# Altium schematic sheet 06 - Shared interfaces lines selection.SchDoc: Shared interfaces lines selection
size A3; PageSetup: Record=PageOptions¦CenterHorizontal=True¦CenterVertical=True¦PrintScale=0.70¦XCorrection=1.00¦YCorrection=1.00¦PrintKind=0¦BorderSize=5000000¦LeftOffset=0¦BottomOffset=0¦Orientation=2¦PaperLength=4200¦PaperWidth=2970¦Scale=100¦PaperSource=7¦PrintQuality=600¦MediaType=1¦DitherType=10¦PaperKind=A4¦PrintScaleMode=1; Author: Juan Anzola; SheetNumber: 6; SheetTotal: 20
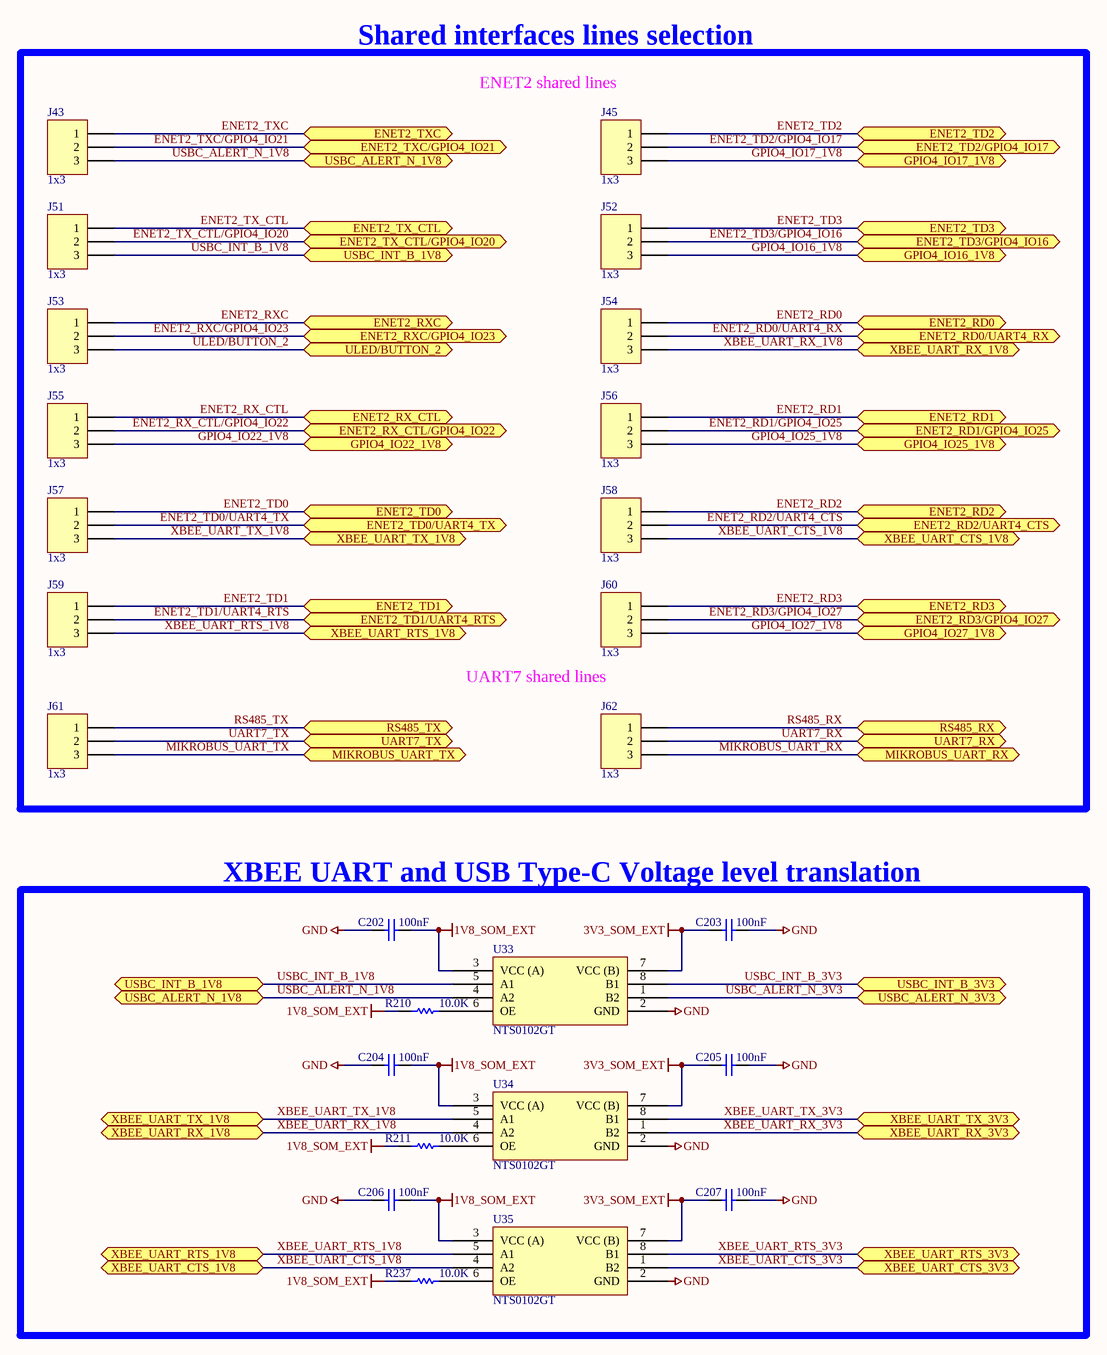
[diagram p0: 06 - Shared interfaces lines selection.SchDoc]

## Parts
C202  100nF  [CAPC1005X55N]
C203  100nF  [CAPC1005X55N]
C204  100nF  [CAPC1005X55N]
C205  100nF  [CAPC1005X55N]
C206  100nF  [CAPC1005X55N]
C207  100nF  [CAPC1005X55N]
J43  1x3  [SAMTEC_TSW-103-07-G-S]
J45  1x3  [SAMTEC_TSW-103-07-G-S]
J51  1x3  [SAMTEC_TSW-103-07-G-S]
J52  1x3  [SAMTEC_TSW-103-07-G-S]
J53  1x3  [SAMTEC_TSW-103-07-G-S]
J54  1x3  [SAMTEC_TSW-103-07-G-S]
J55  1x3  [SAMTEC_TSW-103-07-G-S]
J56  1x3  [SAMTEC_TSW-103-07-G-S]
J57  1x3  [SAMTEC_TSW-103-07-G-S]
J58  1x3  [SAMTEC_TSW-103-07-G-S]
J59  1x3  [SAMTEC_TSW-103-07-G-S]
J60  1x3  [SAMTEC_TSW-103-07-G-S]
J61  1x3  [SAMTEC_TSW-103-07-G-S]
J62  1x3  [SAMTEC_TSW-103-07-G-S]
R210  10.0K  [RESC1005X40N]
R211  10.0K  [RESC1005X40N]
R237  10.0K  [RESC1005X40N]
U33  NTS0102GT  [PSON50P195X100X50-8N]
U34  NTS0102GT  [PSON50P195X100X50-8N]
U35  NTS0102GT  [PSON50P195X100X50-8N]

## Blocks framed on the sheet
Shared interfaces lines selection: J43 J45 J51-J62
XBEE UART and USB Type-C Voltage level translation: C202-C207 R210 R211 R237 U33-U35

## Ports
ENET2_RD0 (bidir), ENET2_RD0/UART4_RX (bidir), ENET2_RD1 (bidir), ENET2_RD1/GPIO4_IO25 (bidir), ENET2_RD2 (bidir), ENET2_RD2/UART4_CTS (bidir), ENET2_RD3 (bidir), ENET2_RD3/GPIO4_IO27 (bidir), ENET2_RX_CTL (bidir), ENET2_RX_CTL/GPIO4_IO22 (bidir), ENET2_RXC (bidir), ENET2_RXC/GPIO4_IO23 (bidir), ENET2_TD0 (bidir), ENET2_TD0/UART4_TX (bidir), ENET2_TD1 (bidir), ENET2_TD1/UART4_RTS (bidir), ENET2_TD2 (bidir), ENET2_TD2/GPIO4_IO17 (bidir), ENET2_TD3 (bidir), ENET2_TD3/GPIO4_IO16 (bidir), ENET2_TX_CTL (bidir), ENET2_TX_CTL/GPIO4_IO20 (bidir), ENET2_TXC (bidir), ENET2_TXC/GPIO4_IO21 (bidir), GPIO4_IO16_1V8 (bidir), GPIO4_IO17_1V8 (bidir), GPIO4_IO22_1V8 (bidir), GPIO4_IO25_1V8 (bidir), GPIO4_IO27_1V8 (bidir), MIKROBUS_UART_RX (bidir), MIKROBUS_UART_TX (bidir), RS485_RX (bidir), RS485_TX (bidir), UART7_RX (bidir), UART7_TX (bidir), ULED/BUTTON_2 (bidir), USBC_ALERT_N_1V8 (bidir), USBC_ALERT_N_3V3 (bidir), USBC_INT_B_1V8 (bidir), USBC_INT_B_3V3 (bidir), XBEE_UART_CTS_1V8 (bidir), XBEE_UART_CTS_3V3 (bidir), XBEE_UART_RTS_1V8 (bidir), XBEE_UART_RTS_3V3 (bidir), XBEE_UART_RX_1V8 (bidir), XBEE_UART_RX_3V3 (bidir), XBEE_UART_TX_1V8 (bidir), XBEE_UART_TX_3V3 (bidir)

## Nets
1V8_SOM_EXT: C202.2 C204.2 C206.2 R210.1 R211.1 R237.1 U33.3(VCC_(A)) U34.3(VCC_(A)) U35.3(VCC_(A))
3V3_SOM_EXT: C203.1 C205.1 C207.1 U33.7(VCC_(B)) U34.7(VCC_(B)) U35.7(VCC_(B))
GND: C202.1 C203.2 C204.1 C205.2 C206.1 C207.2 U33.2(GND) U34.2(GND) U35.2(GND)
ENET2_RD0: J54.1 ; port ENET2_RD0
ENET2_RD0/UART4_RX: J54.2 ; port ENET2_RD0/UART4_RX
ENET2_RD1: J56.1 ; port ENET2_RD1
ENET2_RD1/GPIO4_IO25: J56.2 ; port ENET2_RD1/GPIO4_IO25
ENET2_RD2: J58.1 ; port ENET2_RD2
ENET2_RD2/UART4_CTS: J58.2 ; port ENET2_RD2/UART4_CTS
ENET2_RD3: J60.1 ; port ENET2_RD3
ENET2_RD3/GPIO4_IO27: J60.2 ; port ENET2_RD3/GPIO4_IO27
ENET2_RX_CTL: J55.1 ; port ENET2_RX_CTL
ENET2_RX_CTL/GPIO4_IO22: J55.2 ; port ENET2_RX_CTL/GPIO4_IO22
ENET2_RXC: J53.1 ; port ENET2_RXC
ENET2_RXC/GPIO4_IO23: J53.2 ; port ENET2_RXC/GPIO4_IO23
ENET2_TD0: J57.1 ; port ENET2_TD0
ENET2_TD0/UART4_TX: J57.2 ; port ENET2_TD0/UART4_TX
ENET2_TD1: J59.1 ; port ENET2_TD1
ENET2_TD1/UART4_RTS: J59.2 ; port ENET2_TD1/UART4_RTS
ENET2_TD2: J45.1 ; port ENET2_TD2
ENET2_TD2/GPIO4_IO17: J45.2 ; port ENET2_TD2/GPIO4_IO17
ENET2_TD3: J52.1 ; port ENET2_TD3
ENET2_TD3/GPIO4_IO16: J52.2 ; port ENET2_TD3/GPIO4_IO16
ENET2_TX_CTL: J51.1 ; port ENET2_TX_CTL
ENET2_TX_CTL/GPIO4_IO20: J51.2 ; port ENET2_TX_CTL/GPIO4_IO20
ENET2_TXC: J43.1 ; port ENET2_TXC
ENET2_TXC/GPIO4_IO21: J43.2 ; port ENET2_TXC/GPIO4_IO21
GPIO4_IO16_1V8: J52.3 ; port GPIO4_IO16_1V8
GPIO4_IO17_1V8: J45.3 ; port GPIO4_IO17_1V8
GPIO4_IO22_1V8: J55.3 ; port GPIO4_IO22_1V8
GPIO4_IO25_1V8: J56.3 ; port GPIO4_IO25_1V8
GPIO4_IO27_1V8: J60.3 ; port GPIO4_IO27_1V8
MIKROBUS_UART_RX: J62.3 ; port MIKROBUS_UART_RX
MIKROBUS_UART_TX: J61.3 ; port MIKROBUS_UART_TX
RS485_RX: J62.1 ; port RS485_RX
RS485_TX: J61.1 ; port RS485_TX
UART7_RX: J62.2 ; port UART7_RX
UART7_TX: J61.2 ; port UART7_TX
ULED/BUTTON_2: J53.3 ; port ULED/BUTTON_2
USBC_ALERT_N_1V8: J43.3 U33.4(A2) ; port USBC_ALERT_N_1V8
USBC_ALERT_N_3V3: U33.1(B2) ; port USBC_ALERT_N_3V3
USBC_INT_B_1V8: J51.3 U33.5(A1) ; port USBC_INT_B_1V8
USBC_INT_B_3V3: U33.8(B1) ; port USBC_INT_B_3V3
XBEE_UART_CTS_1V8: J58.3 U35.4(A2) ; port XBEE_UART_CTS_1V8
XBEE_UART_CTS_3V3: U35.1(B2) ; port XBEE_UART_CTS_3V3
XBEE_UART_RTS_1V8: J59.3 U35.5(A1) ; port XBEE_UART_RTS_1V8
XBEE_UART_RTS_3V3: U35.8(B1) ; port XBEE_UART_RTS_3V3
XBEE_UART_RX_1V8: J54.3 U34.4(A2) ; port XBEE_UART_RX_1V8
XBEE_UART_RX_3V3: U34.1(B2) ; port XBEE_UART_RX_3V3
XBEE_UART_TX_1V8: J57.3 U34.5(A1) ; port XBEE_UART_TX_1V8
XBEE_UART_TX_3V3: U34.8(B1) ; port XBEE_UART_TX_3V3
NetR210_2: R210.2 U33.6(OE)
NetR211_2: R211.2 U34.6(OE)
NetR237_2: R237.2 U35.6(OE)

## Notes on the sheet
- (near J45) ENET2 shared lines
- UART7 shared lines

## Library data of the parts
C202-C207 = 1000006: CAP 100nF 16V 10% X7R 0402; Part_Type: Capacitor; Manufacturer: Murata; Manufacturer_Part_Number: GRM155R71C104KA88D; Digi_PN: 14050552; Component_Life_Cycle_State: CAD Reviewed; Area: 0,95; Tolerance: 10
J43 J45 J51-J62 = 1002832: CONN HEADER 3POS .100" SGL GOLD; Part_Type: Connector; Manufacturer: Samtec; Manufacturer_Part_Number: TSW-103-07-G-S; Digi_PN: 00120003; Component_Life_Cycle_State: Pending; Area: 19,3548
R210 R211 R237 = 1000537: RES 10.0K OHM 1/10W 1% 0402 SMD; Part_Type: Resistor; Manufacturer: Panasonic - ECG; Manufacturer_Part_Number: ERJ-2RKF1002X; Digi_PN: 13051084; Component_Life_Cycle_State: CAD Reviewed; Area: 0,95; Power_WV_SRF: 100
U33-U35 = 1002597: IC TRANSLATING TXRX 8XSON; Manufacturer: NXP Semiconductors; Manufacturer_Part_Number: NTS0102GT,115; Digi_PN: 16000138; Component_Life_Cycle_State: Reviewed; Area: 3,9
